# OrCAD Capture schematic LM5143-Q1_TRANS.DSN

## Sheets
1 PAGE1: size Custom; title: LM5143-Q1 3.5-V to 65-V Low IQ, Dual Synchronous Buck; rev: 1.0; note: Datasheet: SNVSB29     EVM: NA; note: Synchronous Step Down Converter
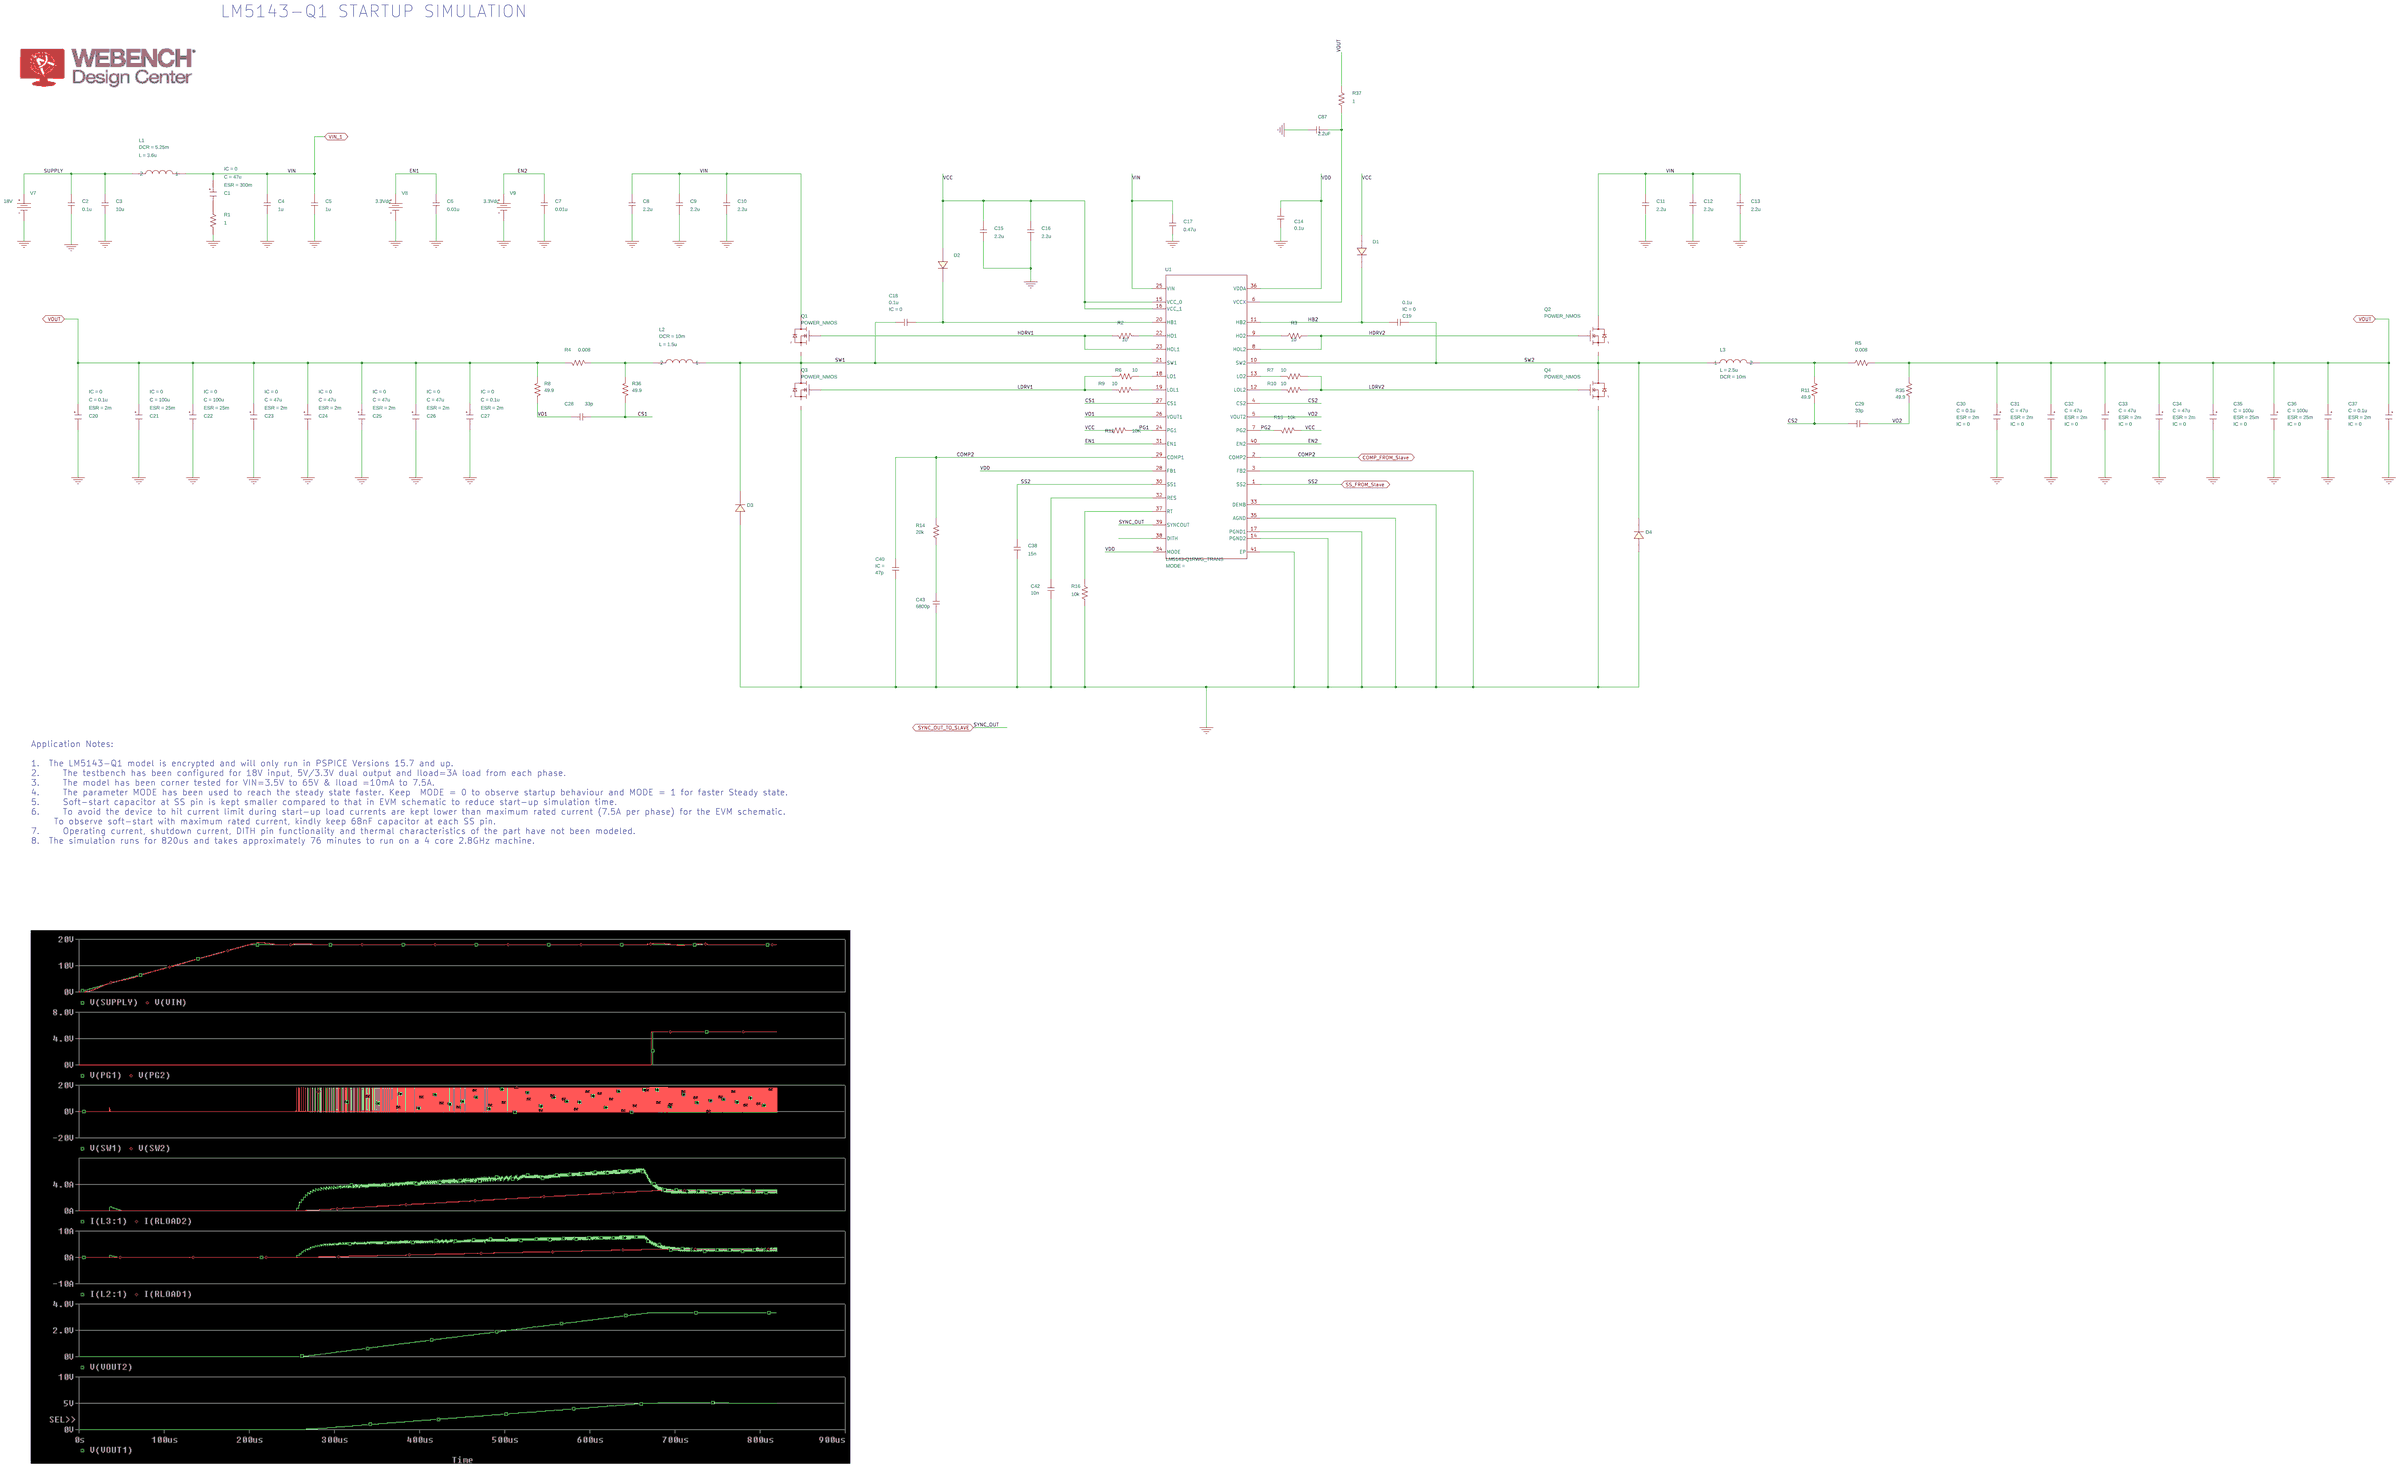
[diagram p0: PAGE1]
2 PAGE2: size Custom
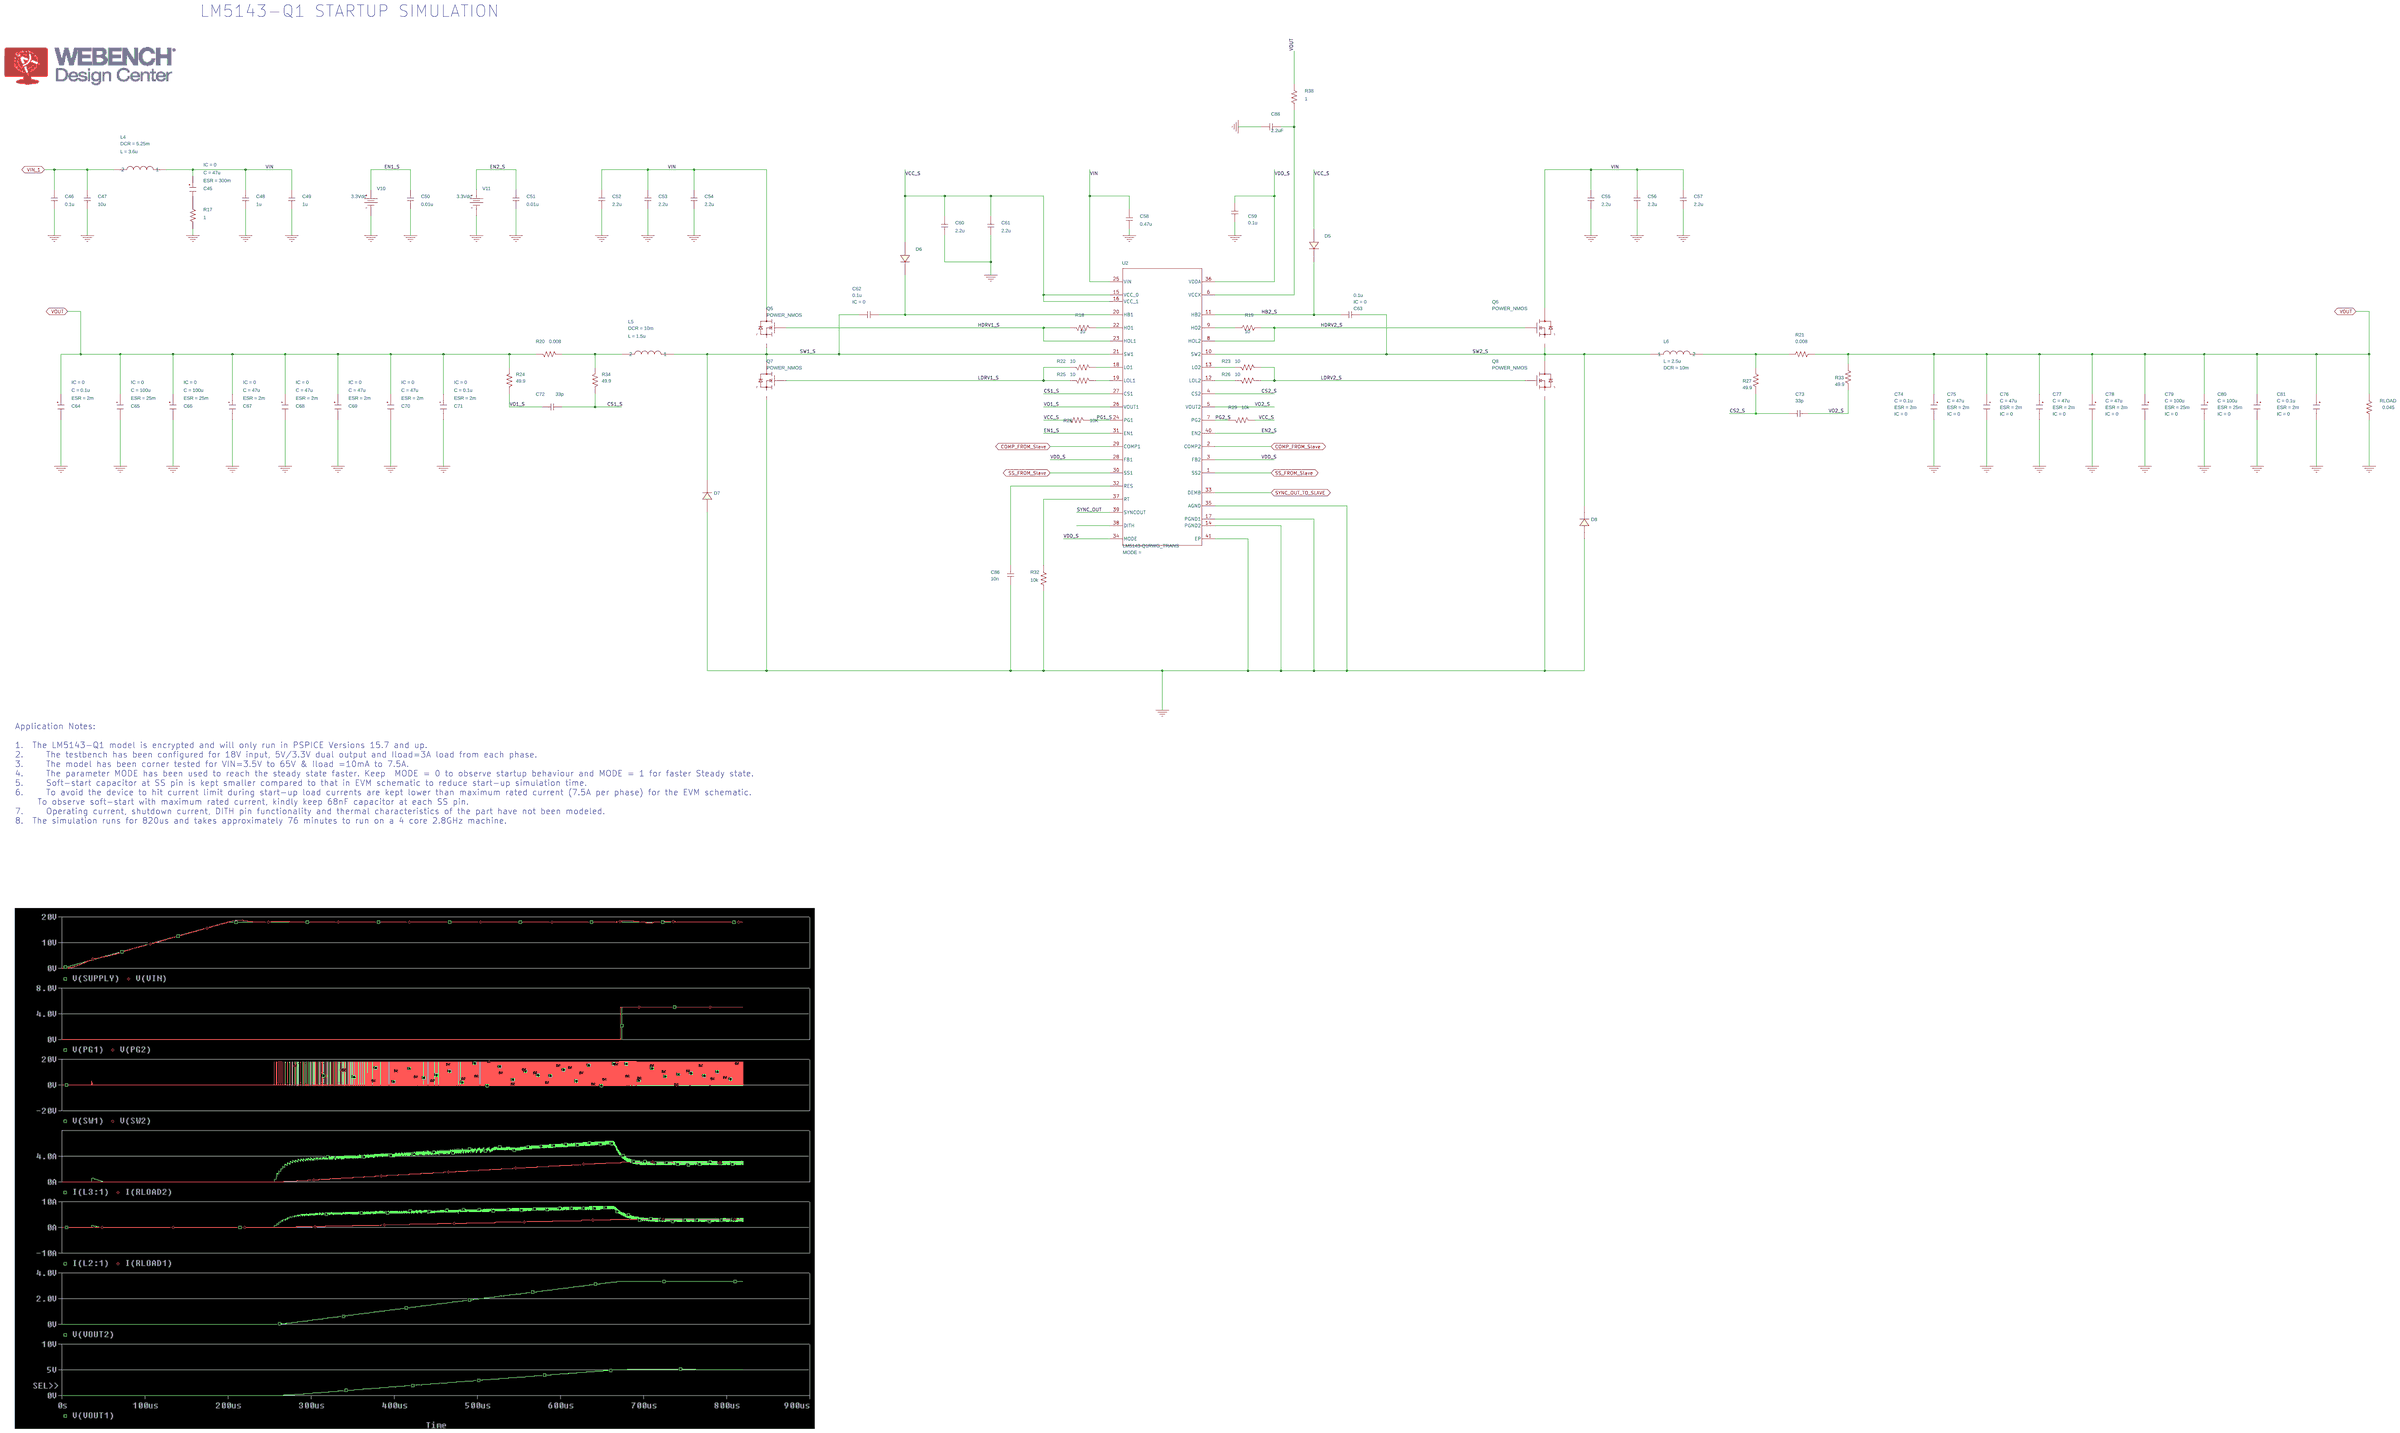
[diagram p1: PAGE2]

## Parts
sheet PAGE1
C1  CESR
C2  0.1u  [RAD/CK05]
C3  10u  [RAD/CK05]
C4  1u  [RAD/CK05]
C5  1u  [RAD/CK05]
C6  0.01u  [RAD/CK05]
C7  0.01u  [cap196]
C8  2.2u  [RAD/CK05]
C9  2.2u  [RAD/CK05]
C10  2.2u  [RAD/CK05]
C11  2.2u  [RAD/CK05]
C12  2.2u  [RAD/CK05]
C13  2.2u  [RAD/CK05]
C14  0.1u  [RAD/CK05]
C15  2.2u  [RAD/CK05]
C16  2.2u  [RAD/CK05]
C17  0.47u  [RAD/CK05]
C18  0.1u  [RAD/CK05]
C19  0.1u  [RAD/CK05]
C20  CESR
C21  CESR
C22  CESR
C23  CESR
C24  CESR
C25  CESR
C26  CESR
C27  CESR
C28  33p  [RAD/CK05]
C29  33p  [RAD/CK05]
C30  CESR
C31  CESR
C32  CESR
C33  CESR
C34  CESR
C35  CESR
C36  CESR
C37  CESR
C38  15n  [RAD/CK05]
C40  47p  [RAD/CK05]
C42  10n  [RAD/CK05]
C43  6800p  [RAD/CK05]
C87  2.2uF  [cap196]
D1  D_D1
D2  D_D1
D3  D_D1
D4  D_D1
L1  LDCR
L2  LDCR
L3  LDCR
Q1  POWER_NMOS
Q2  POWER_NMOS
Q3  POWER_NMOS
Q4  POWER_NMOS
R1  1  [AX/RC05]
R2  10  [AX/RC05]
R3  10  [AX/RC05]
R4  0.008  [AX/RC05]
R5  0.008  [AX/RC05]
R6  10  [AXRC05]
R7  10  [AX/RC05]
R8  49.9  [AX/RC05]
R9  10  [AX/RC05]
R10  10  [AX/RC05]
R11  49.9  [AX/RC05]
R12  10K  [AX/RC05]
R13  10k  [AX/RC05]
R14  20k  [AX/RC05]
R16  10k  [AX/RC05]
R35  49.9  [AX/RC05]
R36  49.9  [AX/RC05]
R37  1  [AXRC05]
U1  LM5143-Q1RWG_TRANS  [RWG0040A]
V7  VDC
V8  VDC
V9  VDC
sheet PAGE2
C45  CESR
C46  0.1u  [RAD/CK05]
C47  10u  [RAD/CK05]
C48  1u  [RAD/CK05]
C49  1u  [RAD/CK05]
C50  0.01u  [RAD/CK05]
C51  0.01u  [RAD/CK05]
C52  2.2u  [RAD/CK05]
C53  2.2u  [RAD/CK05]
C54  2.2u  [RAD/CK05]
C55  2.2u  [RAD/CK05]
C56  2.2u  [RAD/CK05]
C57  2.2u  [RAD/CK05]
C58  0.47u  [RAD/CK05]
C59  0.1u  [RAD/CK05]
C60  2.2u  [RAD/CK05]
C61  2.2u  [RAD/CK05]
C62  0.1u  [RAD/CK05]
C63  0.1u  [RAD/CK05]
C64  CESR
C65  CESR
C66  CESR
C67  CESR
C68  CESR
C69  CESR
C70  CESR
C71  CESR
C72  33p  [RAD/CK05]
C73  33p  [RAD/CK05]
C74  CESR
C75  CESR
C76  CESR
C77  CESR
C78  CESR
C79  CESR
C80  CESR
C81  CESR
C86  10n  [RAD/CK05]
C88  2.2uF  [cap196]
D5  D_D1
D6  D_D1
D7  D_D1
D8  D_D1
L4  LDCR
L5  LDCR
L6  LDCR
Q5  POWER_NMOS
Q6  POWER_NMOS
Q7  POWER_NMOS
Q8  POWER_NMOS
R17  1  [AX/RC05]
R18  10  [AX/RC05]
R19  10  [AX/RC05]
R20  0.008  [AX/RC05]
R21  0.008  [AX/RC05]
R22  10  [AX/RC05]
R23  10  [AX/RC05]
R24  49.9  [AX/RC05]
R25  10  [AX/RC05]
R26  10  [AX/RC05]
R27  49.9  [AX/RC05]
R28  10K  [AX/RC05]
R29  10k  [AX/RC05]
R32  10k  [AX/RC05]
R33  49.9  [AX/RC05]
R34  49.9  [AX/RC05]
R38  1  [AXRC05]
RLOAD  0.045  [AX/RC05]
U2  LM5143-Q1RWG_TRANS  [RWG0040A]
V10  VDC
V11  VDC

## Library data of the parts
C1 C45 = CESR_0: C: 47u; ESR: 300m; IC: 0; PSpiceTemplate: X^@REFDES %IN %OUT @MODEL PARAMS:  ?C|C=@C||C=100u|  ?ESR|ESR=@ESR||ESR=0.01| ?X|X=@X||X=2|  ?IC|IC=@IC||IC=2|; X: 1
C2-C13 C15-C17 C28 C29 C38 C40 C42 C43 C46-C58 C60 C61 C72 C73 C86-C88 = C
C14 C59 = C: IC: 3.4
C18 C19 C62 C63 = C: IC: 0
C20 C27 C30 C37 C64 C71 C74 C81 = CESR_0: C: 0.1u; ESR: 2m; IC: 0; PSpiceTemplate: X^@REFDES %IN %OUT @MODEL PARAMS:  ?C|C=@C||C=100u|  ?ESR|ESR=@ESR||ESR=0.01| ?X|X=@X||X=2|  ?IC|IC=@IC||IC=2|; X: 1
C21 C22 C35 C36 C65 C66 C79 C80 = CESR_0: C: 100u; ESR: 25m; IC: 0; PSpiceTemplate: X^@REFDES %IN %OUT @MODEL PARAMS:  ?C|C=@C||C=100u|  ?ESR|ESR=@ESR||ESR=0.01| ?X|X=@X||X=2|  ?IC|IC=@IC||IC=2|; X: 1
C23-C26 C31-C34 C67-C70 C75-C78 = CESR_0: C: 47u; ESR: 2m; IC: 0; PSpiceTemplate: X^@REFDES %IN %OUT @MODEL PARAMS:  ?C|C=@C||C=100u|  ?ESR|ESR=@ESR||ESR=0.01| ?X|X=@X||X=2|  ?IC|IC=@IC||IC=2|; X: 1
D1-D8 = D_D1
L1 = LDCR: DCR: 5.25m; L: 3.6u
L2 = LDCR_2: DCR: 10m; L: 1.5u
L3 = LDCR_1: DCR: 10m; L: 2.5u
Q1-Q8 = CSD17579Q3A
R1-R14 R16-R29 R32-R38 RLOAD = R
U1 U2 = LM5143-Q1RWG_TRANS
V7 = VDC: DC: 18V
V8-V11 = VDC: DC: 3.3Vdc
L4 = LDCR_2: DCR: 5.25m; L: 3.6u
L5 = LDCR_1: DCR: 10m; L: 1.5u
L6 = LDCR: DCR: 10m; L: 2.5u

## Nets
VCC: C15.1 C16.1 D1.2(A) D2.2(A) R12.1 R13.2 U1.15(VCC_0) U1.16(VCC_1)
VCC_S: C60.1 C61.1 D5.2(A) D6.2(A) R28.1 R29.2 U2.15(VCC_0) U2.16(VCC_1)
VDD: C14.1 U1.28(FB1) U1.34(MODE) U1.36(VDDA)
VDD_S: C59.1 U2.3(FB2) U2.28(FB1) U2.34(MODE) U2.36(VDDA)
VIN: C45.1(IN) C48.1 C49.1 C52.1 C53.1 C54.1 C55.1 C56.1 C57.1 C58.2 L4.1 Q5.3(drain) Q6.3(drain) U2.25(VIN)
VIN_1: C1.1(IN) C4.1 C5.1 C8.1 C9.1 C10.1 C11.1 C12.1 C13.1 C17.2 C46.2 C47.2 L1.1 L4.2 Q1.3(drain) Q2.3(drain) U1.25(VIN)
0: C2.1 C3.1 C4.2 C5.2 C6.1 C7.1 C8.2 C9.2 C10.2 C11.2 C12.2 C13.2 C14.2 C15.2 C16.2 C17.1 C20.2(OUT) C21.2(OUT) C22.2(OUT) C23.2(OUT) C24.2(OUT) C25.2(OUT) C26.2(OUT) C27.2(OUT) C30.2(OUT) C31.2(OUT) C32.2(OUT) C33.2(OUT) C34.2(OUT) C35.2(OUT) C36.2(OUT) C37.2(OUT) C38.2 C40.2 C42.1 C43.1 C46.1 C47.1 C48.2 C49.2 C50.1 C51.1 C52.2 C53.2 C54.2 C55.2 C56.2 C57.2 C58.1 C59.2 C60.2 C61.2 C64.2(OUT) C65.2(OUT) C66.2(OUT) C67.2(OUT) C68.2(OUT) C69.2(OUT) C70.2(OUT) C71.2(OUT) C74.2(OUT) C75.2(OUT) C76.2(OUT) C77.2(OUT) C78.2(OUT) C79.2(OUT) C80.2(OUT) C81.2(OUT) C86.1 C87.1 C88.1 D3.2(A) D4.2(A) D7.2(A) D8.2(A) Q3.1(source) Q4.1(source) Q7.1(source) Q8.1(source) R1.1 R16.2 R17.1 R32.2 RLOAD.2 U1.3(FB2) U1.14(PGND2) U1.17(PGND1) U1.33(DEMB) U1.35(AGND) U1.41(EP) U2.14(PGND2) U2.17(PGND1) U2.35(AGND) U2.41(EP) V7.1(-) V8.1(-) V9.1(-) V10.1(-) V11.1(-)
COMP_FROM_Slave: C40.1 R14.2 U1.2(COMP2) U1.29(COMP1) U2.2(COMP2) U2.29(COMP1)
CS1: C28.2 R36.1 U1.27(CS1)
CS1_S: C72.2 R34.1 U2.27(CS1)
CS2: C29.2 R11.1 U1.4(CS2)
CS2_S: C73.2 R27.1 U2.4(CS2)
EN1: C6.2 U1.31(EN1) V8.0(+)
EN1_S: C50.2 U2.31(EN1) V10.0(+)
EN2: C7.2 U1.40(EN2) V9.0(+)
EN2_S: C51.2 U2.40(EN2) V11.0(+)
HB2: C19.1 D1.1(C) U1.11(HB2)
HB2_S: C63.1 D5.1(C) U2.11(HB2)
HDRV1: Q1.2(gate) R2.2 U1.23(HOL1)
HDRV1_S: Q5.2(gate) R18.2 U2.23(HOL1)
HDRV2: Q2.2(gate) R3.2 U1.8(HOL2)
HDRV2_S: Q6.2(gate) R19.2 U2.8(HOL2)
LDRV1: Q3.2(gate) R6.1 R9.2
LDRV1_S: Q7.2(gate) R22.2 R25.2
LDRV2: Q4.2(gate) R7.1 R10.1
LDRV2_S: Q8.2(gate) R23.1 R26.1
PG1: R12.2 U1.24(PG1)
PG1_S: R28.2 U2.24(PG1)
PG2: R13.1 U1.7(PG2)
PG2_S: R29.1 U2.7(PG2)
SS_FROM_Slave: C38.1 U1.1(SS2) U1.30(SS1) U2.1(SS2) U2.30(SS1)
SUPPLY: C2.2 C3.2 L1.2 V7.0(+)
SW1: C18.2 D3.1(C) L2.1 Q1.1(source) Q3.3(drain) U1.21(SW1)
SW1_S: C62.2 D7.1(C) L5.1 Q5.1(source) Q7.3(drain) U2.21(SW1)
SW2: C19.2 D4.1(C) L3.1 Q2.1(source) Q4.3(drain) U1.10(SW2)
SW2_S: C63.2 D8.1(C) L6.1 Q6.1(source) Q8.3(drain) U2.10(SW2)
SYNC_OUT: U2.39(SYNCOUT)
SYNC_OUT_TO_SLAVE: U1.39(SYNCOUT) U2.33(DEMB)
VO1: C28.1 R8.1 U1.26(VOUT1)
VO1_S: C72.1 R24.1 U2.26(VOUT1)
VO2: C29.1 R35.1 U1.5(VOUT2)
VO2_S: C73.1 R33.1 U2.5(VOUT2)
VOUT: C20.1(IN) C21.1(IN) C22.1(IN) C23.1(IN) C24.1(IN) C25.1(IN) C26.1(IN) C27.1(IN) C30.1(IN) C31.1(IN) C32.1(IN) C33.1(IN) C34.1(IN) C35.1(IN) C36.1(IN) C37.1(IN) C64.1(IN) C65.1(IN) C66.1(IN) C67.1(IN) C68.1(IN) C69.1(IN) C70.1(IN) C71.1(IN) C74.1(IN) C75.1(IN) C76.1(IN) C77.1(IN) C78.1(IN) C79.1(IN) C80.1(IN) C81.1(IN) R4.1 R5.1 R8.2 R20.1 R21.1 R24.2 R33.2 R35.2 R37.2 R38.2 RLOAD.1
N46716: R10.2 U1.12(LOL2)
N46722: R7.2 U1.13(LO2)
N61694: R3.1 U1.9(HO2)
N69334: C87.2 R37.1 U1.6(VCCX)
N86263: R16.1 U1.37(RT)
N88026: C42.2 U1.32(RES)
N94411: C43.2 R14.1
N119731: R2.1 U1.22(HO1)
N145587: L2.2 R4.2 R36.2
N156761: C18.1 D2.1(C) U1.20(HB1)
N16785518: L3.2 R5.2 R11.2
N16806978: C62.1 D6.1(C) U2.20(HB1)
N16807003: R25.1 U2.19(LOL1)
N16807006: L6.2 R21.2 R27.2
N16807029: R22.1 U2.18(LO1)
N16807059: R26.2 U2.12(LOL2)
N16807060: R23.2 U2.13(LO2)
N16807067: R19.1 U2.9(HO2)
N16807088: R32.1 U2.37(RT)
N16807091: C86.2 U2.32(RES)
N16807115: R18.1 U2.22(HO1)
N16807148: L5.2 R20.2 R34.2
N16819450: R9.1 U1.19(LOL1)
N16820302: R6.2 U1.18(LO1)
N16820579: C1.2(OUT) R1.2
N16827985: C45.2(OUT) R17.2
N16828076: C88.2 R38.1 U2.6(VCCX)

Not connected (* = marked no-connect by the designer): U1 38(DITH); U2 38(DITH)

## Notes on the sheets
sheet 1
- LM5143-Q1 STARTUP SIMULATION
- Application Notes:
  1.  The LM5143-Q1 model is encrypted and will only run in PSPICE Versions 15.7 and up.
  2.	  The testbench has been configured for 18V input, 5V/3.3V dual output and Iload=3A load from each phase.
  3.	  The model has been corner tested for VIN=3.5V to 65V & Iload =10mA to 7.5A.
  4.	  The parameter MODE has been used to reach the steady state faster. Keep  MODE = 0 to observe startup behaviour and MODE = 1 for faster Steady state.
  5.	  Soft-start capacitor at SS pin is kept smaller compared to that in EVM schematic to reduce start-up simulation time.
  6.	  To avoid the device to hit current limit during start-up load currents are kept lower than maximum rated current (7.5A per phase) for the EVM schematic.
       To observe soft-start with maximum rated current, kindly keep 68nF capacitor at each SS pin.
  7.	  Operating current, shutdown current, DITH pin functionality and thermal characteristics of the part have not been modeled.
  8.  The simulation runs for 820us and takes approximately 76 minutes to run on a 4 core 2.8GHz machine.
sheet 2
- LM5143-Q1 STARTUP SIMULATION
- Application Notes:
  1.  The LM5143-Q1 model is encrypted and will only run in PSPICE Versions 15.7 and up.
  2.	  The testbench has been configured for 18V input, 5V/3.3V dual output and Iload=3A load from each phase.
  3.	  The model has been corner tested for VIN=3.5V to 65V & Iload =10mA to 7.5A.
  4.	  The parameter MODE has been used to reach the steady state faster. Keep  MODE = 0 to observe startup behaviour and MODE = 1 for faster Steady state.
  5.	  Soft-start capacitor at SS pin is kept smaller compared to that in EVM schematic to reduce start-up simulation time.
  6.	  To avoid the device to hit current limit during start-up load currents are kept lower than maximum rated current (7.5A per phase) for the EVM schematic.
       To observe soft-start with maximum rated current, kindly keep 68nF capacitor at each SS pin.
  7.	  Operating current, shutdown current, DITH pin functionality and thermal characteristics of the part have not been modeled.
  8.  The simulation runs for 820us and takes approximately 76 minutes to run on a 4 core 2.8GHz machine.
